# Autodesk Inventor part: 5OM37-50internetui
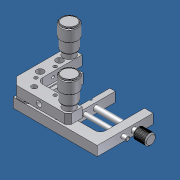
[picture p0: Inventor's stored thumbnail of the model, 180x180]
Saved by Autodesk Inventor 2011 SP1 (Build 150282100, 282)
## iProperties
Created: 2011-06
Part Number: 5OM37-50internetui
Document SubType Name: Modeling
Designer: Darius
Density: 1 g/cm^3
Author: Darius
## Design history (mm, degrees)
feature "Base1"
body "Solid1"
